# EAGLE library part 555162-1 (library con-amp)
AMP connector
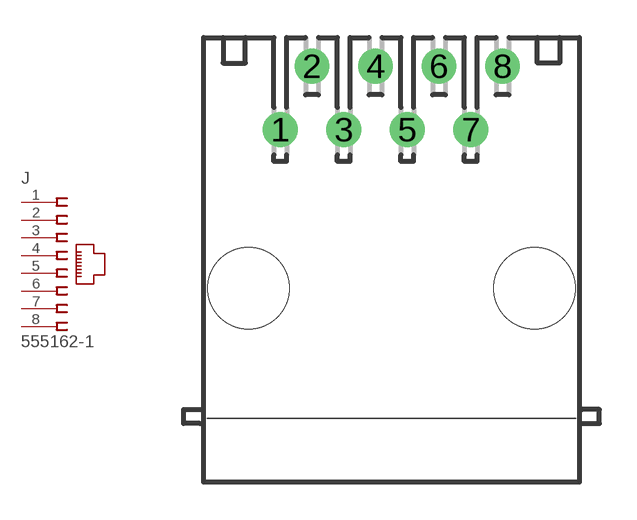
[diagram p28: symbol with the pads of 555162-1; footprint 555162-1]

Designator prefix J

## 555162-1 (MF: TYCO ELECTRONICS; MPN: 5555162-1; OC_FARNELL: 1557716; OC_NEWARK: 42K8758)  [555162-1]
1  1  pas
2  2  pas
3  3  pas
4  4  pas
5  5  pas
6  6  pas
7  7  pas
8  8  pas

## Footprint 555162-1 (pad centres in mm)
Modular Jack with Panel Stops
drill 0.889 round: 1 -4.445,5.207; 2 -3.175,7.747; 3 -1.905,5.207; 4 -0.635,7.747; 5 0.635,5.207; 6 1.905,7.747; 7 3.175,5.207; 8 4.445,7.747
hole 3.251 at -5.715,-1.143
hole 3.251 at 5.715,-1.143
